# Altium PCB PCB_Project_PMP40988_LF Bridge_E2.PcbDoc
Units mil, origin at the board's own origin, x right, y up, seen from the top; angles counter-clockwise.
Board outline 1299.21 x 1322.83 mil, 2 copper layers (Top Layer, Bottom Layer), stack 64.8 mil thick; 14 components, 7 nets, 30 pads, 453 vias.
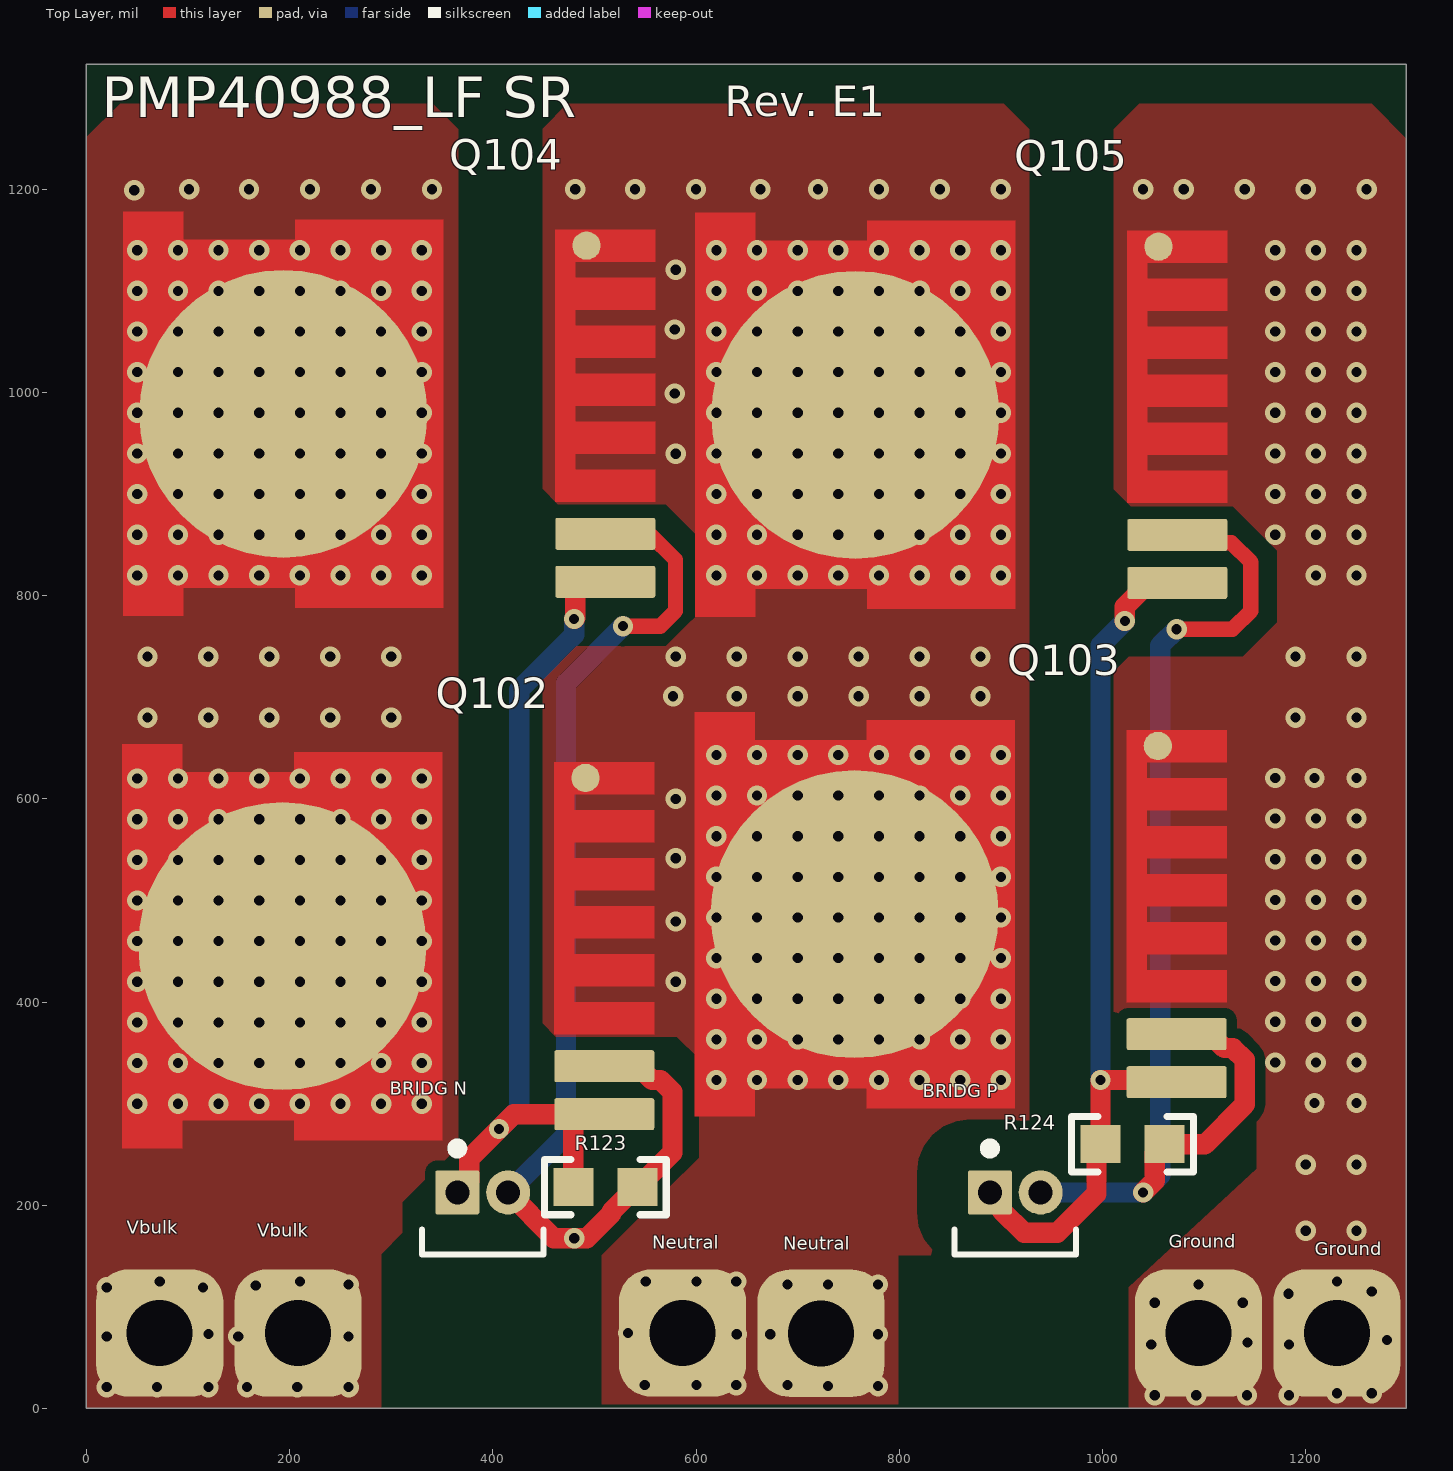
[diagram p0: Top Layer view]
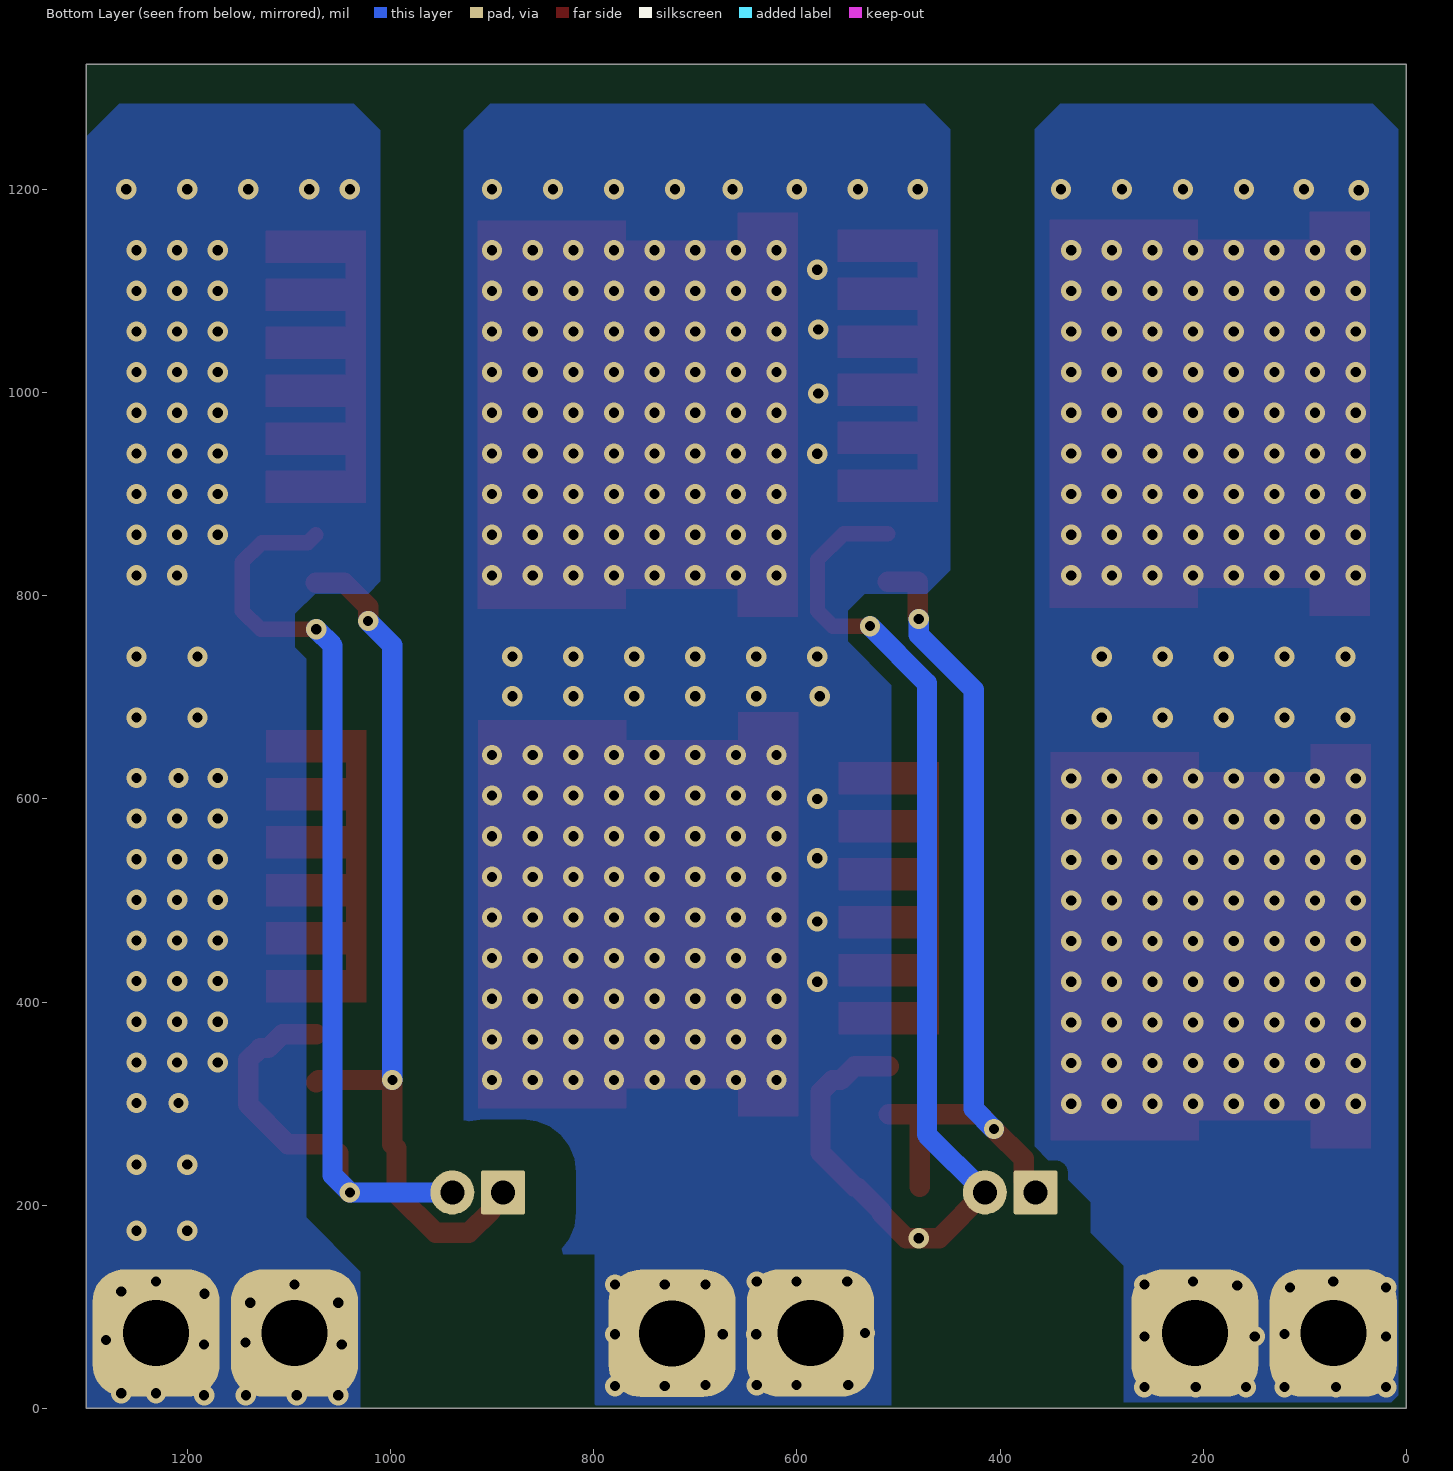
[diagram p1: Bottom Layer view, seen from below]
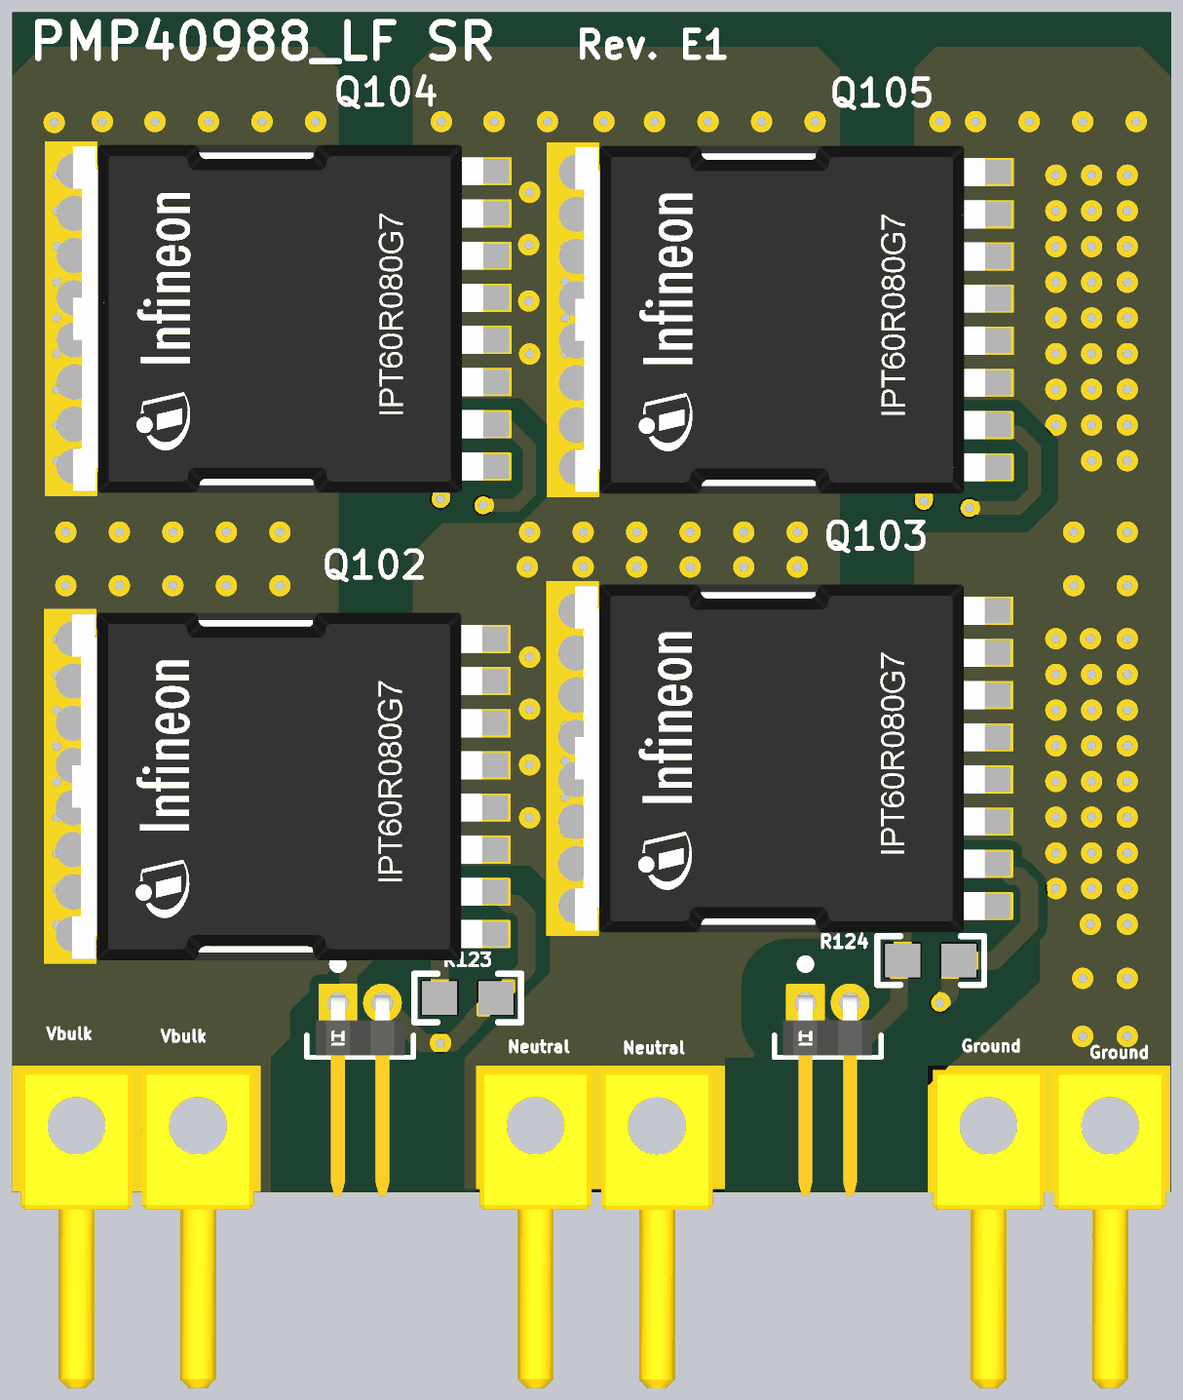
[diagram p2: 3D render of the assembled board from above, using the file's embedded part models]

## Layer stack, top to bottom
Top Solder: solder mask 0.4, Solder Resist, Dk 3.5
Top Layer: signal copper 2.8
Dielectric1: core 59.2, FR-4 High Tg, Dk 4.8
Bottom Layer: signal copper 2.8
Bottom Solder: solder mask 0.4, Solder Resist, Dk 3.5

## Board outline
0,0 0,1322.83 1299.21,1322.83 1299.21,0 925.2,0 767.72,0 393.7,0 278.35,0

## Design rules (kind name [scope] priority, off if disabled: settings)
AcuteAngle [All] p1: minimum=4.50000000000000E+0001 checktracksonly=FALSE
AssemblyTestPointUsage [All] p1: valid=2
Clearance Clearance_3 [InNet('EARTH') vs Not InNet('EARTH') And Not InNet('12VS')] p1: gap=200 ignorepadtopadclearanceinfootprint=FALSE except(0: Arc-Hole Track-Hole SMDPad-Hole THPad-Hole Via-Hole Fill-Hole Poly-Hole Region-Hole Text-Hole)
Clearance Clearance_1 [InNetClass('HV') vs InNetClass('MV')] p2: gap=25 ignorepadtopadclearanceinfootprint=FALSE except(0: Arc-Hole Track-Hole SMDPad-Hole THPad-Hole Via-Hole Fill-Hole Poly-Hole Region-Hole Text-Hole)
Clearance Clearance_2 [InNetClass('HV') vs Not InNetClass('HV')] p3: gap=50 ignorepadtopadclearanceinfootprint=FALSE except(0: Arc-Hole Track-Hole SMDPad-Hole THPad-Hole Via-Hole Fill-Hole Poly-Hole Region-Hole Text-Hole)
Clearance Clearance_Keepouts [((IsTrack Or IsArc) And Not InPoly) And IsFree and IsKeepOut vs ((IsTrack Or IsArc) And Not InPoly) And IsFree and IsKeepOut] p4: gap=0 ignorepadtopadclearanceinfootprint=FALSE
Clearance Clearance_BoardEdge_MountingHoles [OnCopper and InComponentClass('Mounting Holes') vs IsKeepOut] p5: gap=40 ignorepadtopadclearanceinfootprint=FALSE except(0: Arc-Hole Track-Hole SMDPad-Hole THPad-Hole Via-Hole Fill-Hole Poly-Hole Region-Hole Text-Hole)
Clearance Clearance_BoardEdge_Poly [OnCopper and InPoly vs IsKeepOut] p6: gap=25 ignorepadtopadclearanceinfootprint=FALSE except(0: Arc-Hole Track-Hole SMDPad-Hole THPad-Hole Via-Hole Fill-Hole Poly-Hole Region-Hole Text-Hole)
Clearance Clearance_BoardEdge [OnCopper and Not InComponentClass('Logo') and not InComponentClass('FiducialMark') and not InRegion(1000,500,4000,800) and Not IsKeepout vs IsKeepOut] p7: gap=75 ignorepadtopadclearanceinfootprint=FALSE except(0: Arc-Hole Track-Hole SMDPad-Hole THPad-Hole Via-Hole Fill-Hole Poly-Hole Region-Hole Text-Hole)
Clearance Clearance_Poly [InPolygon] p8: gap=10 ignorepadtopadclearanceinfootprint=FALSE except(0: Arc-Hole Track-Hole SMDPad-Hole THPad-Hole Via-Hole Fill-Hole Poly-Hole Region-Hole Text-Hole)
Clearance [All] p9: gap=7.87 ignorepadtopadclearanceinfootprint=TRUE except(0: Arc-Hole Track-Hole SMDPad-Hole THPad-Hole Via-Hole Fill-Hole Poly-Hole Region-Hole Text-Hole)
ComponentClearance ComponentClearance_HeatSink [Identifier = 'Heat Sink'] p1: gap=0 collisioncheckmode=3 verticalgap=0 showdistances=FALSE
ComponentClearance ComponentClearance_MountingHoles_FiducialMarks [InComponentClass('Mounting Holes') vs InComponentClass('FiducialMark')] p2: gap=20 collisioncheckmode=3 verticalgap=10 showdistances=FALSE
ComponentClearance ComponentClearance_Shunt [InComponentClass('Header') vs InComponentClass('Shunt')] p3: gap=0 collisioncheckmode=3 verticalgap=0 showdistances=FALSE
ComponentClearance ComponentClearance_Logo [InComponentClass('Logo')] p4: gap=5 collisioncheckmode=3 verticalgap=10 showdistances=FALSE
ComponentClearance ComponentClearance_ScrewToNut [(HasFootprint('NY PMS 440 0025 PH')) vs (HasFootprint('Keystone_1902C'))] p5: gap=20 collisioncheckmode=3 verticalgap=100000 showdistances=FALSE
ComponentClearance ComponentClearance_MountingHoles [InComponentClass('Mounting Holes')] p6: gap=20 collisioncheckmode=3 verticalgap=10 showdistances=FALSE
ComponentClearance ComponentClearance_SmallPassives [HasFootprint('0201*') or HasFootprint('0402*') or HasFootprint('0508') or HasFootprint('0603*') or HasFootprint('0612') or HasFootprint('0805*') or HasFootprint('0815*') or HasFootprint('0830*') or HasFootprint('1206*') or HasFootprint('1210*') or HasFootprint('1808*') or HasFootprint('1812*') or HasFootprint('1825*') or HasFootprint('2010*') or HasFootprint('2220*') or HasFootprint('2225*') or HasFootprint('2512*') or HasFootprint('2728*') or HasFootprint('3518*') vs HasFootprint('0201*') or HasFootprint('0402*') or HasFootprint('0508') or HasFootprint('0603*') or HasFootprint('0612') or HasFootprint('0805*') or HasFootprint('0815*') or HasFootprint('0830*') or HasFootprint('1206*') or HasFootprint('1210*') or HasFootprint('1808*') or HasFootprint('1812*') or HasFootprint('1825*') or HasFootprint('2010*') or HasFootprint('2220*') or HasFootprint('2225*') or HasFootprint('2512*') or HasFootprint('2728*') or HasFootprint('3518*')] p7: gap=20 collisioncheckmode=3 verticalgap=20 showdistances=FALSE
ComponentClearance ComponentClearance_THtoSMT [IsThruComponent vs IsSMTComponent] p8: gap=10 collisioncheckmode=3 verticalgap=10 showdistances=FALSE
ComponentClearance ComponentClearance_THtoTH [IsThruComponent vs IsThruComponent] p9: gap=10 collisioncheckmode=3 verticalgap=10 showdistances=FALSE
ComponentClearance [All] p10: gap=10 collisioncheckmode=3 verticalgap=10 showdistances=FALSE
DiffPairsRouting [All] p1: maxlimit=100 minlimit=10 mostfreqgap=10 toplayer_minwidth=15 toplayer_maxwidth=15 toplayer_prefwidth=15 bottomlayer_minwidth=15 bottomlayer_maxwidth=15 bottomlayer_prefwidth=15 maxuncoupledlength=1000
FabricationTestPointUsage TestPointUsage [All] p1: valid=2 allowmultiple=FALSE
FabricationTestpoint Testpoint [All] p1: side=3 testpointundercomponent=TRUE minsize=40 maxsize=100 preferedsize=60 minholesize=0 maxholesize=40 preferedholesize=32 testpointgrid=1 allowsidetop=TRUE allowsidebottom=TRUE usegrid=TRUE gridtolerance=0.01
FanoutControl Fanout_LCC [IsLCC] p1: bgadir=Out bgaviamode=Centered fanoutstyle=Auto fanoutdirection=Alternating viagrid=1 // Fanout_LCC (Default Rule)
FanoutControl Fanout_BGA [IsBGA] p2: bgadir=Out bgaviamode=Centered fanoutstyle=Auto fanoutdirection=Alternating viagrid=1 // Fanout_BGA (Default Rule)
FanoutControl Fanout_Default [All] p4: bgadir=Out bgaviamode=Centered fanoutstyle=Auto fanoutdirection=Alternating viagrid=1 // Fanout_Default (Default Rule)
FanoutControl Fanout_Small [(CompPinCount < 5)] p5: bgadir=Out bgaviamode=Centered fanoutstyle=Auto fanoutdirection=OutThenIn viagrid=1 // Fanout_Small (Default Rule)
Height [All] p1: minheight=0 maxheight=3000 prefheight=500
HoleSize [All] p1: absolutevalues=TRUE maxlimit=251 minlimit=7 maxpercent=80.000 minpercent=20.000
MinimumAnnularRing MinimumAnnularRing_ThermalPadVias [IsVia and InAnyComponent] p1: minimumring=5.91
MinimumAnnularRing [All] p2: minimumring=4.9
MinimumSolderMaskSliver MinimumSolderMaskSliver_Logo [InComponentClass('Logo') vs InComponentClass('Logo')] p1: minsoldermaskwidth=0.7
MinimumSolderMaskSliver [All] p2: minsoldermaskwidth=2
PlaneConnect [All] p1: planeconnectstyle=Direct reliefexpansion=10 reliefentries=4 reliefconductorwidth=10 reliefairgap=10
PolygonConnect [All] p1: connectstyle=Direct reliefconductorwidth=10 reliefentries=4 polygonreliefangle="90 Angle" airgapwidth=10
RoutingVias ThermalPadVias [IsVia and InAnyComponent] p1: holewidth=7.87 width=19.68 viastyle="Through Hole" minholewidth=7.87 minwidth=19.68 maxholewidth=12.99 maxwidth=23.62
RoutingVias [All] p2: holewidth=16 width=34 viastyle="Through Hole" minholewidth=7.87 minwidth=20 maxholewidth=40 maxwidth=65
SilkToBoardRegionClearance [Not ((IsComment or IsDesignator) And (Hide <> 'False')) and not InRegion(1000,500,4000,800)] p1:
SilkToSilkClearance SilkToSilkClearance_Pb-FreeLogo [(HasFootprint('Pb-Free_Overlay_Medium') OR HasFootprint('Pb-Free_Overlay_Small')) vs (HasFootprint('Pb-Free_Overlay_Medium') OR HasFootprint('Pb-Free_Overlay_Small'))] p1: silktosilkclearance=0
SilkToSilkClearance [All] p2: silktosilkclearance=1
SilkToSolderMaskClearance "Silk to Solder Mask Opening" [All] p1: minsilkscreentomaskgap=1 clearancetoexposedcopper=FALSE
SolderMaskExpansion [All] p1: expansion=1.97 istentingtop=FALSE
Width [All] p1: maxlimit=100 minlimit=6 preferedwidth=10 checkconnectedcopper=TRUE
14 further rules are at their usual default settings.

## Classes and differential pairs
net class HV: +BRDG_N -BRDG_N Neutral Vbulk
component class "PCB_Project_PMP40988_LF Bridge": "BRIDG N" "BRIDG P" Ground Neutral Q102 Q103 Q104 Q105 R123 R124 Vbulk

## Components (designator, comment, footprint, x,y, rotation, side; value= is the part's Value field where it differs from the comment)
"BRIDG N" "M50-3930242" FP-M50-3930242_HDR2-MFG 390,173.23 r0 top
"BRIDG P" "M50-3930242" FP-M50-3930242_HDR2-MFG 914.18,173.23 r0 top
Ground "3621-0-32-15-00-00-08-0" Mill-Max_3621-0-32-xx-00-00-08-0 1230.71,-19.68 r0 top
Ground "3621-0-32-15-00-00-08-0" Mill-Max_3621-0-32-xx-00-00-08-0 1094.49,-19.68 r0 top
Neutral "3621-0-32-15-00-00-08-0" Mill-Max_3621-0-32-xx-00-00-08-0 722.83,-20 r0 top
Neutral "3621-0-32-15-00-00-08-0" Mill-Max_3621-0-32-xx-00-00-08-0 586.61,-19.68 r0 top
Q102 "IPT60R022S7XTMA1" FP-IPT60R080G7XTMA1_HSOF-8-MFG 299,455 r90 top
Q103 "IPT60R022S7XTMA1" FP-IPT60R080G7XTMA1_HSOF-8-MFG 862.37,486.5 r90 top
Q104 "IPT60R022S7XTMA1" FP-IPT60R080G7XTMA1_HSOF-8-MFG 300,979 r90 top
Q105 "IPT60R022S7XTMA1" FP-IPT60R080G7XTMA1_HSOF-8-MFG 863,978 r90 top
R123 "RC0603FR-07100KL" 0603 510.63,218 r180 top value=100k
R124 "RC0603FR-07100KL" 0603 1029.61,260.07 r180 top value=100k
Vbulk "3621-0-32-15-00-00-08-0" Mill-Max_3621-0-32-xx-00-00-08-0 72.05,-19.68 r0 top
Vbulk "3621-0-32-15-00-00-08-0" Mill-Max_3621-0-32-xx-00-00-08-0 208.27,-19.68 r0 top

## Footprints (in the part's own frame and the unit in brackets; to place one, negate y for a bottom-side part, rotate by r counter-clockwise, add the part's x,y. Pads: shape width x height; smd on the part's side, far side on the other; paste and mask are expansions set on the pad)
0603 [mm] "0603 from SM-752 data"
  rect 1x0.95 smd: 1(-0.8,0) 2(0.8,0)
  silkscreen extent -1.52,-0.69 1.52,0.69, body extent -0.87,-0.47 0.87,0.47, height 1
FP-IPT60R080G7XTMA1_HSOF-8-MFG [mm]
  rrect13% 0.8x2.5 smd paste-1000 mask+0: 1(-4.2,-5.35) 2(-3,-5.35)
  round 0.709 smd paste-1000 mask+0: 3-4-5-6-7-8(4.206,-4.881)
  round 7.2 smd paste-1000 mask+0: 9(0,2.7)
  Top Layer region: -4.85,-1.3 4.85,-1.3 4.85,2.4 4.35,2.4 4.35,5.2 5.05,5.2 5.05,6.7 -5.05,6.7 -5.05,5.2 -4.35,5.2 -4.35,2.4 -4.85,2.4
  Top Layer region: -2.2,-4.1 4.6,-4.1 4.6,-6.6 3.8,-6.6 3.8,-4.6 3.4,-4.6 3.4,-6.6 2.6,-6.6 2.6,-4.6 2.2,-4.6 2.2,-6.6 1.4,-6.6 1.4,-4.6 1,-4.6 1,-6.6 0.2,-6.6 0.2,-4.6 -0.2,-4.6 -0.2,-6.6 -1,-6.6 -1,-4.6 -1.4,-4.6 -1.4,-6.6 -2.2,-6.6 -2.2,-4.1
  body extent -5.15,-6.7 5.15,6.8, height 0.25
FP-M50-3930242_HDR2-MFG [mm]
  rrect9% 1.1x1.1 hole 0.6 paste-1000 mask+0: 1(-0.635,1)
  round 1.1 hole 0.6 paste-1000 mask+0: 2(0.635,1)
  silkscreen extent -1.52,-0.55 1.52,2.22, body extent -1.62,-4.85 1.62,1.65, height 0.25
Mill-Max_3621-0-32-xx-00-00-08-0 [mm] "PCB Pin, 0.04\" DIA, R/A, Edge-Mount"
  rrect50% 3.18x3.18 hole 1.65: 1(0,2.388)
  body extent -1.59,-5.06 1.59,3.98, height 1.57

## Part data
"BRIDG N" "BRIDG P": library part CMP-0097272-1, "Conn Unshrouded HDR 2 POS 1.27mm Solder RA Through Hole Box", Current_A=1A, Digikey Part Number=952-3614-ND, Manufacturer=Harwin, Mouser Part Number=855-M50-3930242, Operating Temperature Range="-40°C to +105°C"
Ground Ground Neutral Neutral Vbulk Vbulk: library part CMP-0082316-1, "PCB Pin, 0.04\" DIA, Edge-Mount", Manufacturer=Mill-Max, Supplier Part Number 1=575-3621032150000
Q102 Q103 Q104 Q105: library part CMP-0086487-1, "MOSFET N-CH 650V 23A HSOF-8", Manufacturer=Infineon
R123 R124: library part CMP-0022735-5, "RES, 100 k, 1%, 0.1 W, 0603", Manufacturer=Yageo, Power_W=100mW, Supplier Part Number 1=311-100KHRCT-ND, TempCo="100 ppm/C", Tolerance_%=1%, Value2=0.1W, Value_Code=100k

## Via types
v1: diameter 20, hole 10, Top Layer to Bottom Layer, 453 vias

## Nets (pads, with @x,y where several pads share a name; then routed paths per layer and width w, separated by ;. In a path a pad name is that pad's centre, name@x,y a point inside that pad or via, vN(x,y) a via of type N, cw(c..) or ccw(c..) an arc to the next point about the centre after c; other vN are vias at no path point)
+BRDG_N: "BRIDG N.1" Q102.1 Q104.1 R123.2 | length 862.4
  Top Layer w20: 365,212.6 376.65,224.25 376.65,245.65 v1(406,275) 420.65,289.65 Q102.1@484.88,289.65 ; R123.2 479.13,283.9 Q102.1@484.88,289.65 ; v1(480,777) 481.1,778.1 481.1,813.65 Q104.1 ; Q102.1 Q102.1@484.88,289.65
  Bottom Layer w20: v1(406,275) 426,295 426,707.42 480,761.42 v1(480,777)
+BRDG_P: "BRIDG P.1" Q103.1 Q105.1 R124.2 | length 867.2
  Top Layer w20: 889.18,212.37 900.83,200.72 900.83,194.82 922.81,172.84 955.55,172.84 994.08,211.37 994.08,256.04 R124.2 v1(998.12,323.27) 1070.87,323.27 Q103.1 ; v1(1022,775) 1022,789.2 1045.45,812.65 Q105.1
  Bottom Layer w20: v1(998.12,323.27) 998.12,751.12 v1(1022,775)
-BRDG_N: "BRIDG N.2" Q102.2 Q104.2 R123.1 | length 1145.8
  Top Layer w15: Q104.2 554.11,860.89 579.62,835.38 579.62,784.8 564.82,770 v1(528,770)
  Top Layer w20: 415,212.6 460.02,167.58 492.38,167.58 516.69,191.9 516.69,193.55 541.14,218 543.11,218 576.72,251.61 576.72,311.6 565.05,323.27 556.72,323.27 543.09,336.89 Q102.2
  Bottom Layer w20: 415,212.6 472,269.6 472,714 v1(528,770)
  other v1: 480.1,167.58
-BRDG_P: "BRIDG P.2" Q103.2 Q105.2 R124.1 | length 1120.4
  Top Layer w15: v1(1073,767) 1128,767 1146,785 1146,833 1127,852 1081.52,852 Q105.2
  Top Layer w20: v1(1040,212.6) 1051.43,224.02 R124.1@1051.43,251.37 ; R124.1 1100.97,260.07 1140.09,299.19 1140.09,343.09 1128.42,354.76 1120.09,354.76 1106.46,368.39 Q103.2
  Bottom Layer w20: 959.82,212.6 v1(1040,212.6) 1057,229.6 1057,751 v1(1073,767)
Neutral: Neutral.1 Q102.3-4-5-6-7-8 Q103.9 Q104.3-4-5-6-7-8 Q105.9
  other v1: 730,22 779,22 549.5,23 600.5,23 639.5,23 690,23 640,73 673,73 779,73 533,74.32 690,122 730,122 779,122 550.5,125 600.5,125 639.5,125 620,323.27 660,323.27 700,323.27 740,323.27 780,323.27 820,323.27 860,323.27 900,323.27 620,363.27 660,363.27 700,363.27 740,363.27 780,363.27 820,363.27 860,363.27 900,363.27 620,403.27 660,403.27 700,403.27 740,403.27 780,403.27 820,403.27 860,403.27 900,403.27 580,420 620,443.27 660,443.27 700,443.27 740,443.27 780,443.27 820,443.27 860,443.27 900,443.27 580,479.27 620,483.27 660,483.27 700,483.27 740,483.27 780,483.27 820,483.27 860,483.27 900,483.27 620,523.27 660,523.27 700,523.27 740,523.27 780,523.27 820,523.27 860,523.27 900,523.27 580,541.61 620,563.27 660,563.27 700,563.27 740,563.27 780,563.27 820,563.27 860,563.27 900,563.27 580,600 620,603.27 660,603.27 700,603.27 740,603.27 780,603.27 820,603.27 860,603.27 900,603.27 620,643.27 660,643.27 700,643.27 740,643.27 780,643.27 820,643.27 860,643.27 900,643.27 577.44,701 640,701 700,701 760,701 820,701 880,701 580,740 640,740 700,740 760,740 820,740 880,740 620,820 660,820 700,820 740,820 780,820 820,820 860,820 900,820 620,860 660,860 700,860 740,860 780,860 820,860 860,860 900,860 620,900 660,900 700,900 740,900 780,900 820,900 860,900 900,900 580,939.63 620,940 660,940 700,940 740,940 780,940 820,940 860,940 900,940 620,980 660,980 700,980 740,980 780,980 820,980 860,980 900,980 579,999 620,1020 660,1020 700,1020 740,1020 780,1020 820,1020 860,1020 900,1020 620,1060 660,1060 700,1060 740,1060 780,1060 820,1060 860,1060 900,1060 579,1062 620,1100 660,1100 700,1100 740,1100 780,1100 820,1100 860,1100 900,1100 580,1120.73 620,1140 660,1140 700,1140 740,1140 780,1140 820,1140 860,1140 900,1140 481.1,1200 540,1200 600,1200 663.28,1200 720,1200 780,1200 840,1200 900,1200
PGND: Ground.1 Q103.3-4-5-6-7-8 Q105.3-4-5-6-7-8
  other v1: 1051.43,13 1092.31,13 1142.31,13 1183.42,13 1230.71,15 1265,15 1048,63 1183.42,63 1142.84,65 1280,67.32 1051.43,104 1138,104 1183,113 1265,115 1094.49,122 1230.71,125 1200,175 1250,175 1200,240 1250,240 1208.63,300.6 1250,300.6 1170,340.6 1210,340.6 1250,340.6 1170,380.6 1210,380.6 1250,380.6 1170,420.6 1210,420.6 1250,420.6 1170,460.6 1210,460.6 1250,460.6 1170,500.6 1210,500.6 1250,500.6 1170,540.6 1210,540.6 1250,540.6 1170,580.6 1210,580.6 1250,580.6 1170,620.6 1208.63,620.6 1250,620.6 1190,680 1250,680 1190,740 1250,740 1210,820 1250,820 1170,860 1210,860 1250,860 1170,900 1210,900 1250,900 1170,940 1210,940 1250,940 1170,980 1210,980 1250,980 1170,1020 1210,1020 1250,1020 1170,1060 1210,1060 1250,1060 1170,1100 1210,1100 1250,1100 1170,1140 1210,1140 1250,1140 1040,1200 1080,1200 1140,1200 1200,1200 1260,1200
Vbulk: Q102.9 Q104.9 Vbulk.1
  other v1: 20,21 69.42,21 120,21 158,21 207.42,21 258,21 20,71 149.39,71 258,71 120,73.17 20,119.22 114.7,119.22 166.58,121 258,122 72.05,125 210,125 50,300 90,300 130,300 170,300 210,300 250,300 290,300 330,300 50,340 90,340 130,340 170,340 210,340 250,340 290,340 330,340 50,380 90,380 130,380 170,380 210,380 250,380 290,380 330,380 50,420 90,420 130,420 170,420 210,420 250,420 290,420 330,420 50,460 90,460 130,460 170,460 210,460 250,460 290,460 330,460 50,500 90,500 130,500 170,500 210,500 250,500 290,500 330,500 50,540 90,540 130,540 170,540 210,540 250,540 290,540 330,540 50,580 90,580 130,580 170,580 210,580 250,580 290,580 330,580 50,620 90,620 130,620 170,620 210,620 250,620 290,620 330,620 60,680 120,680 180,680 240,680 300,680 60,740 120,740 180,740 240,740 300,740 50,820 90,820 130,820 170,820 210,820 250,820 290,820 330,820 50,860 90,860 130,860 170,860 210,860 250,860 290,860 330,860 50,900 90,900 130,900 170,900 210,900 250,900 290,900 330,900 50,940 90,940 130,940 170,940 210,940 250,940 290,940 330,940 50,980 90,980 130,980 170,980 210,980 250,980 290,980 330,980 50,1020 90,1020 130,1020 170,1020 210,1020 250,1020 290,1020 330,1020 50,1060 90,1060 130,1060 170,1060 210,1060 250,1060 290,1060 330,1060 50,1100 90,1100 130,1100 170,1100 210,1100 250,1100 290,1100 330,1100 50,1140 90,1140 130,1140 170,1140 210,1140 250,1140 290,1140 330,1140 47,1199 101,1200 160,1200 220,1200 280,1200 340,1200

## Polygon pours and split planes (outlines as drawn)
PGND on Top Layer "Top Layer-No Net 1" (solid, remove dead copper, pour order 2): 1265,1284 1299.21,1249.79 1299.21,0 1026,0 1026,119.22 1152,236 1152,349 1132.61,368.39 1029.61,368.39 1011,387 1011,725 1026,740 1138,740 1172,774 1172,844 1128,888 1027.8,888 1011,904.8 1011,1259 1036,1284
Vbulk on Top Layer "Top Layer-No Net" (solid, remove dead copper, pour order 0): 33,1284 341,1284 366,1259 366,258 311,203 311,173 290,152 290,0 0,0 0,1251
Neutral on Top Layer "Top Layer-No Net 2" (solid, remove dead copper, pour order 4): 903,1284 928,1259 928,273 873,218 873,169 855,151 799,151 799,4 506.98,4 506.98,150.98 603,247 603,344 581,366 462,366 449,379 449,717 482,750 570,750 599,779 599,861 570,890 464,890 449,905 449,1259.58 473.42,1284
Neutral on Bottom Layer "Bottom Layer-No Net 1" (solid, remove dead copper, pour order 10): 902,1284 474,1284 449,1259 449,825 472,802 533,802 550,785 550,755 506.98,711.98 506.98,3 798,3 799,4 799,152 857,152 874,169 874,218 928,272 928,1258
PGND on Bottom Layer "Bottom Layer-No Net" (solid, remove dead copper, pour order 8): 1010,1258 1010,814 1022,802 1074,802 1094,782 1094,749 1083,738 1083,188.02 1029.61,134.63 1029.61,0 1299.21,0 1299.21,1251.79 1267,1284 1036,1284
Vbulk on Bottom Layer "Top Layer-No Net" (solid, remove dead copper, pour order 6): 33,1284 341,1284 366,1259 366,258 311,203 311,173 278.35,140.35 278.35,6 15,6 8,13 8,1259

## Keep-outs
Keep-Out Layer:
  text ".Layer_Name" at -945,-1745.76 h60

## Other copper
Top Layer:
  text ".Layer_Name" at -945,-1745.76 h60
Bottom Layer:
  text ".Layer_Name" at -945,-1745.76 h60

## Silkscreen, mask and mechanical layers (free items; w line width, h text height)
Top Overlay:
  text "Rev. E1" at 628,1272 h30
  text "PMP40988_LF SR" at 15,1271 h40
  text ".Layer_Name" at -945,-1745.76 h60
Bottom Overlay:
  text ".Layer_Name" at -945,-1745.76 h60
Top Paste:
  text ".Layer_Name" at -945,-1745.76 h60
Bottom Paste:
  text ".Layer_Name" at -945,-1745.76 h60
Top Solder:
  rectangle: 1026,0 1298,142
  rectangle: 520,0 799,142
  rectangle: 0,1 278.35,142
  text ".Layer_Name" at -945,-1745.76 h60
  text ".Layer_Name" at -945,-1745.76 h60
Bottom Solder:
  rectangle: 1018,814 1270,1268
  rectangle: 554,707 926,865
  rectangle: 470,859 926,1268
  rectangle: 1027.8,0 1299,140.35
  rectangle: 521.5,1 818,143
  rectangle: 0,1 290,142
  rectangle: 33,247 356,1268
  rectangle: 533,250 926,707
  rectangle: 1101,252 1270,818
  text ".Layer_Name" at -945,-1745.76 h60
Drill Guide:
  text ".Layer_Name" at -945,-1745.76 h60
M1 Board Outline:
  the board outline again, w10
  text ".Layer_Name" at -945,-1745.76 h60
M2 Board Dimensions:
  rectangle: -1397,-1287.27 -1022,-1162.27
  rectangle: -1522,-1162.27 -1397,-1037.27
  lines w7: -1522,-1162.27 -522,-1162.27 ; -1397,-1287.27 -1397,-1037.27 ; -1272,-1287.27 -1272,-1037.27 ; -1022,-1287.27 -1022,-1037.27 ; -772,-1287.27 -772,-1037.27 ; -1522,-1287.27 -1522,-1037.27 -522,-1037.27 -522,-1287.27 -1522,-1287.27
  text ".Layer_Name" at -945,-1745.76 h60
M3 3D STEP Top:
  text ".Layer_Name" at -945,-1745.76 h60
M4 3D STEP Bottom:
  text ".Layer_Name" at -945,-1745.76 h60
M5 Assembly Top:
  lines w10: -1814,-1817.43 4786,-1817.43 ; -1814,-1614.1 4788,-1614.1 ; -1814,-1410.77 -1814,-2020.77 2191,-2020.77 4788,-2020.77 4788,-1410.77 -1813.5,-1410.77 -1813.5,-2020.77 -238,-2020.77 ; 651,-2020.77 651,-1410.77 ; 1918,-1614.1 1918,-1410.77 ; 2758,-1614.1 2758,-1410.77 ; 3380,-2027.27 3380,-1824.43
  text "COMPONENTS MARKED 'DNP' SHOULD NOT BE POPULATED." at -368.5,-1205.77 h60
  text "ASSEMBLY VARIANT:" at -369,-1321.27 h60
  text ".VariantName" at 667,-1321.27 h60
  text "PCB VIEWED FROM TOP SIDE" at -1750.5,-1542.93 h60
  text "BOARD #:" at 726,-1542.93 h60
  text ".PRJ_Number" at 1271.5,-1542.93 h60
  text "REV:" at 2116,-1542.93 h60
  text ".PCB_Rev" at 2407.5,-1542.93 h60
  text "SVN REV:" at 2954,-1542.93 h60
  text ".VersionControl_RevNumber" at 3460,-1542.93 h60
  text "TID #:" at 726,-1746.27 h60
  text ".TID" at 1271.5,-1746.27 h60
  text "PLOT NAME =" at -1750.5,-1951.6 h60
  text ".plot_File_Name" at -945,-1951.6 h60
  text "GENERATED    :" at 728,-1951.6 h60
  text ".Print_Date" at 1597.5,-1951.6 h60
  text ".Print_Time" at 2326.5,-1951.6 h60
  text "TEXAS INSTRUMENTS" at 3591,-1951.6 h60
M6 Assembly Bottom:
  lines w10: -1814.5,-1614.6 4787.5,-1614.6 ; -1812.5,-1817.93 4787.5,-1817.93 ; -406.5,-2027.77 -406.5,-1824.93 ; 215.5,-1614.6 215.5,-1411.27 ; 1055.5,-1614.6 1055.5,-1411.27 ; 2322.5,-2021.27 2322.5,-1411.27 ; 3211.5,-2021.27 4787,-2021.27 4787,-1411.27 -1814.5,-1411.27 -1814.5,-2021.27 782.5,-2021.27 4787.5,-2021.27 4787.5,-1411.27
  text "COMPONENTS MARKED 'DNP' SHOULD NOT BE POPULATED." at 4580,-1205.27 h60
  text ".VariantName" at 3536,-1321.27 h60
  text "ASSEMBLY VARIANT:" at 4575,-1321.27 h60
  text ".VersionControl_RevNumber" at -486.5,-1543.43 h60
  text "SVN REV:" at 19.5,-1543.43 h60
  text ".PCB_Rev" at 566,-1543.43 h60
  text "REV:" at 857.5,-1543.43 h60
  text ".PRJ_Number" at 1702,-1543.43 h60
  text "BOARD #:" at 2247.5,-1543.43 h60
  text "PCB VIEWED FROM BOTTOM SIDE" at 4724,-1543.43 h60
  text ".TID" at 1702,-1746.77 h60
  text "TID #:" at 2247.5,-1746.77 h60
  text "TEXAS INSTRUMENTS" at -617.5,-1952.1 h60
  text ".Print_Time" at 647,-1952.1 h60
  text ".Print_Date" at 1376,-1952.1 h60
  text "GENERATED    :" at 2245.5,-1952.1 h60
  text ".plot_File_Name" at 3918.5,-1952.1 h60
  text "PLOT NAME =" at 4724,-1952.1 h60
M9 Title Sheet:
  drawing of 57 lines, arcs and shapes, not listed
  text "1" at -782.16,7149.23 h70
  text "2" at 1713.5,7149.23 h70
  text "3" at 4202.84,7149.23 h70
  text "4" at 6709.51,7149.23 h70
  text "5" at 9208.5,7149.23 h70
  text "6" at 11713.5,7149.23 h70
  text "A" at -1938.5,6006.23 h70
  text "A" at 12861.5,6006.23 h70
  text "B" at -1938.5,3626.23 h70
  text "B" at 12861.5,3626.23 h70
  text "C" at -1938.5,1251.23 h70
  text "C" at 12861.5,1251.23 h70
  text "PROJECT TITLE:" at 9821.5,-609.77 h45
  text ".PRJ_Title" at 9871.5,-743.09 h70
  text "DESIGNED FOR:" at 9821.5,-910.77 h45
  text ".PRJ_Customer" at 9871.5,-1050.77 h70
  text "D" at -1938.5,-1118.77 h70
  text "D" at 12861.5,-1118.77 h70
  text "FILE NAME:" at 9821.5,-1210.77 h45
  text ".PCB_File_Name_No_Path" at 9871.5,-1330.77 h70
  text "Texas Instruments (TI) and/or its licensors do not warrant the accuracy or completeness of this specification" at 4852,-1492.61 h45
  text "ENGINEER:" at 9821.5,-1500.77 h45
  text "LAYOUT BY:" at 11326.5,-1500.77 h45
  text "or any information contained therein. TI and/or its licensors do not warrant that this design will meet" at 4807.01,-1605.27 h45
  text ".PRJ_Engineer" at 9871.5,-1655.76 h70
  text ".PCB_Layout" at 11377,-1655.76 h70
  text "the specifications, will be suitable for your application or fit for any particular purpose, or will operate in" at 4807.01,-1717.94 h45
  text ".Layer_Name" at -945,-1745.76 h60
  text "ALTIUM DESIGNER VERSION:" at 11326.5,-1810.77 h45
  text "an implementation. TI and/or its licensors do not warrant that the design is production worthy. You should" at 4807.01,-1830.6 h45
  text "completely validate and test your design implementation to confirm the system functionality for your application." at 4852,-1943.27 h45
  text ".print_Scale" at 9871.5,-1944.09 h70
  text ".Application_BuildNumber" at 11377,-1944.09 h70
  text "1" at -782.16,-2150.77 h70
  text "2" at 1713.5,-2150.77 h70
  text "3" at 4202.84,-2150.77 h70
  text "4" at 6709.51,-2150.77 h70
  text "5" at 9208.5,-2150.77 h70
  text "6" at 11713.5,-2150.77 h70
M10 Fab Notes:
  drawing of 189 lines, arcs and shapes, not listed
  text "DESIGN INFORMATION" at 10860.02,5468.91 h60
  text "MIN. TRACK WIDTH:" at 10215.46,5336.78 h60
  text "8" at 11311.7,5336.78 h60
  text "MIL" at 11466.46,5336.78 h60
  text "7.874" at 11145.32,5215.09 h60
  text "MIN. CLEARANCE:" at 10215.46,5212.65 h60
  text "MIL" at 11466.46,5212.65 h60
  text "MIN. VIA PAD SIZE:" at 10215.46,5088.53 h60
  text "24" at 11281.71,5088.53 h60
  text "MIL" at 11466.46,5088.53 h60
  text "0.05mm (2MIL)" at 10910.46,4958.63 h60
  text "MINIMUM ANNULAR RING" at 9886.23,4950.41 h60
  text "EXTERNAL" at 11618.46,4950.41 h60
  text "PER" at 10086.23,4840.28 h60
  text "IPC-D-275 CLASS 2 LEVEL C" at 10306.23,4840.28 h60
  text "MIL, HOLES" at 11794.46,4739.8 h60
  text "+/-" at 11402,4731.22 h60
  text "+/-" at 12256,4731.22 h60
  text "REGISTRATION TOLERANCES:" at 9886.23,4730.15 h60
  text "METAL" at 11086,4730.15 h60
  text "5" at 11662.2,4730.15 h60
  text "3" at 12495.2,4730.15 h60
  text "MIL" at 12611.46,4730.15 h60
  text "HOLE SIZE TOLERANCE (UNLESS OTHERWISE SPECIFIED):" at 9886.23,4631.84 h60
  text "+/-" at 12256,4628.96 h60
  text "3" at 12495.2,4627.9 h60
  text "MIL" at 12611.46,4627.9 h60
  text "MATERIAL:" at 9811.46,4490.25 h60
  text "FR-4 High Tg" at 10797.9,4361.73 h60
  text "X" at 10653.46,4353.74 h60
  text "FR-408" at 10232.46,4349.22 h60
  text "OTHER" at 11720.46,4349.22 h60
  text "62 MIL (1.6mm) +/-10%" at 10552.56,4206.19 h60
  text "X" at 10432.46,4203.74 h60
  text "THICKNESS:" at 9886.23,4197.97 h60
  text "OTHER" at 11837.46,4197.97 h60
  text "TOLERANCE:" at 9886.23,4059.65 h60
  text "X" at 10734.46,4059.65 h60
  text "ANSI IPC-6012 TYPE 3 CLASS 2" at 10912.48,4059.65 h60
  text "OTHER +/-" at 10912.46,3915.47 h60
  text "BOW & TWIST:" at 9886.23,3770.28 h60
  text "X" at 10734.46,3770.28 h60
  text "ANSI IPC-6012 TYPE 3 CLASS 2" at 10912.48,3770.28 h60
  text "OTHER +/-" at 10912.46,3623.58 h60
  text "DRILLING:" at 9811.46,3492.96 h60
  text "NC_DRILL FILES" at 11572.46,3387.77 h60
  text "REFERENCE:" at 9886.23,3383.84 h60
  text "X" at 10543.46,3383.74 h60
  text "AS SHOWN" at 10721.46,3383.84 h60
  text "X" at 11444.46,3383.84 h60
  text "OTHER" at 11870.46,3241.58 h60
  text "PTH COPPER THICKNESS:" at 9885.91,3238.06 h60
  text "X" at 11025.14,3238.06 h60
  text "20-30 um" at 11153.14,3238.06 h60
  text "BOARD FINISH:" at 9811.46,3090.46 h60
  text "SILKSCREEN:" at 9966.68,2980.33 h60
  text "X" at 10924.46,2980.33 h60
  text "TOP" at 11041.46,2980.33 h60
  text "X" at 11434.46,2980.33 h60
  text "BOTTOM" at 11552.46,2980.33 h60
  text "SILKSCREEN COLOR:" at 9966.68,2825.14 h60
  text "X" at 10923.46,2825.14 h60
  text "WHITE" at 11041.46,2825.14 h60
  text "OTHER" at 11552.46,2825.14 h60
  text "X" at 11054.46,2681.69 h60
  text "GREEN" at 11172.46,2681.69 h60
  text "OTHER" at 11790.46,2681.69 h60
  text "SOLDER RESIST COLOR:" at 9966.68,2674.83 h60
  text "X" at 11054.46,2527.44 h60
  text "MATTE" at 11172.46,2527.44 h60
  text "SEMI-GLOSS" at 11790,2526.8 h60
  text "IMMERSION GOLD (ENIG)" at 10872.46,2354.67 h60
  text "ENEPIG" at 12210,2347.45 h60
  text "SURFACE FINISH:" at 9811.46,2346.45 h60
  text "X" at 10694.46,2346.45 h60
  text "IMM. TIN/SILVER OR EQUIV" at 10141,2209.13 h60
  text "OTHER" at 11572.46,2205.2 h60
  text "ARRAY/PANEL:" at 9811.46,2049.82 h60
  text "CUT AND TRIM PER M1 BOARD OUTLINE" at 10872.46,2041.6 h60
  text "N.C. ROUTE" at 10872.46,1905.63 h60
  text "X" at 11560.46,1905.63 h60
  text "V. SCORE" at 11738.46,1905.63 h60
  text "CERTIFICATION:" at 9811.46,1776.5 h60
  text "MATERIALS AND WORKMANSHIP FOR ALL PCBS" at 10536.46,1776.5 h60
  text "TO MEET OR EXCEED THE REQUIREMENTS OF:" at 10536.46,1682.44 h60
  text "X" at 10173.97,1553.81 h60
  text "ANSI IPC-A-600F CLASS ->" at 10301.96,1553.81 h60
  text "X" at 11949.97,1553.81 h60
  text "2" at 12059.96,1553.81 h60
  text "1" at 11744.96,1552.32 h60
  text "3" at 12413.96,1552.32 h60
  text "X" at 10985.97,1406.13 h60
  text "RoHS" at 11113.96,1406.13 h60
  text "OTHER" at 11758.36,1406.13 h60
  text "PER ORDER" at 12155.42,1406.13 h60
  text "ALL BOARDS MUST MEET OR EXCEED UL94-V0 REQUIREMENTS." at 9839,1252.3 h60
  text "PCB MUST BEAR THE UL94V-0 UL REGISTERED MATERIAL ID NUMBER" at 9839,1136.24 h60
  text "ADDITIONAL REQUIREMENTS:" at 9811.46,966.81 h60
  text "MICROSECTION:" at 9886.23,859.69 h60
  text "YES" at 10791.96,859.69 h60
  text "REQUIRED" at 11653.46,715.35 h60
  text "BARE BOARD ELEC. TEST:" at 9886.23,712.5 h60
  text "NONE" at 11191.96,712.5 h60
  text "X" at 11535.46,712.5 h60
  text "PER ORDER" at 12245.46,712.5 h60
  text "XX MIL VIAS REQUIRE NON-CONDUCTIVE FILL AND PLANARIZE" at 10054.38,507.55 h59
  text "XX MIL VIAS REQUIRE CONDUCTIVE FILL AND PLANARIZE" at 10062.38,403.58 h60
  text "OUTER XX MIL TRACES REQUIRE 50 OHM SINGLE-ENDED IMPEDANCE" at 10061.39,240.19 h58
  text "LAYER 2 & 3 (INNER LAYERS) XX MIL WIDE, XX MIL SPACE / TRACES REQUIRE 100 OHM DIFFERENTIAL IMPEDANCE" at 10053.39,4.48 h60
  text ".Layer_Name" at -945,-1745.76 h60
M11 Gerber Information:
  lines w10: -1814,-1817.43 4786,-1817.43 ; -1814,-1614.1 4788,-1614.1 ; -1814,-1410.77 -1814,-2020.77 2191,-2020.77 4788,-2020.77 4788,-1410.77 -1813.5,-1410.77 -1813.5,-2020.77 -238,-2020.77 ; 651,-2020.77 651,-1410.77 ; 1918,-1614.1 1918,-1410.77 ; 2758,-1614.1 2758,-1410.77 ; 3380,-2027.27 3380,-1824.43
  text "ALL ARTWORK VIEWED FROM TOP SIDE" at -1750.5,-1542.93 h60
  text "BOARD #:" at 726,-1542.93 h60
  text ".PRJ_Number" at 1271.5,-1542.93 h60
  text "REV:" at 2116,-1542.93 h60
  text ".PCB_Rev" at 2407.5,-1542.93 h60
  text "SVN REV:" at 2954,-1542.93 h60
  text ".VersionControl_RevNumber" at 3460,-1542.93 h60
  text "LAYER NAME =" at -1750.5,-1745.76 h60
  text "TID #:" at 726,-1746.27 h60
  text ".TID" at 1271.5,-1746.27 h60
  text "PLOT NAME =" at -1750.5,-1951.6 h60
  text ".plot_File_Name" at -945,-1951.6 h60
  text "GENERATED    :" at 728,-1951.6 h60
  text ".Print_Date" at 1597.5,-1951.6 h60
  text ".Print_Time" at 2326.5,-1951.6 h60
  text "TEXAS INSTRUMENTS" at 3591,-1951.6 h60
M12 Stackup:
  drawing of 191 lines, arcs and shapes, not listed
  text "Layer" at 8299.59,6987.67 h60
  text "Name" at 8709.51,6987.67 h60
  text "Material" at 9639.25,6987.67 h60
  text "Thickness" at 10499.02,6987.67 h60
  text "Constant" at 11148.85,6987.67 h60
  text "Board Layer Stack" at 11718.71,6987.67 h60
  text "Top Overlay" at 8709.51,6867.67 h60
  text "Top Solder" at 8709.51,6747.67 h60
  text "Solder Resist" at 9639.25,6747.67 h60
  text "0.40mil" at 10499.02,6747.67 h60
  text "3.5" at 11148.85,6747.67 h60
  text "1" at 8299.59,6627.67 h60
  text "Top Layer" at 8709.51,6627.67 h60
  text "2.80mil" at 10499.02,6627.67 h60
  text "Dielectric1" at 8709.51,6507.67 h60
  text "FR-4 High Tg" at 9639.25,6507.67 h60
  text "59.20mil" at 10499.02,6507.67 h60
  text "4.8" at 11148.85,6507.67 h60
  text "2" at 8299.59,6387.67 h60
  text "Bottom Layer" at 8709.51,6387.67 h60
  text "2.80mil" at 10499.02,6387.67 h60
  text "Bottom Solder" at 8709.51,6267.67 h60
  text "Solder Resist" at 9639.25,6267.67 h60
  text "0.40mil" at 10499.02,6267.67 h60
  text "3.5" at 11148.85,6267.67 h60
  text "Bottom Overlay" at 8709.51,6147.67 h60
  text ".Layer_Name" at -945,-1745.76 h60
M13 Component Bodies Top:
  text ".Layer_Name" at -945,-1745.76 h60
M14 Component Bodies Bottom:
  text ".Layer_Name" at -945,-1745.76 h60
M15 Courtyards Top:
  text ".Layer_Name" at -945,-1745.76 h60
M16 Courtyards Bottom:
  text ".Layer_Name" at -945,-1745.76 h60
Drill Drawing:
  circle w10: c3841.72,2154.38 r27.63
  lines w10: 3814.09,2264.88 3827.9,2264.88 3841.72,2251.07 3855.53,2264.88 3869.34,2264.88 3855.53,2278.7 3869.34,2292.51 3855.53,2292.51 3841.72,2306.32 3827.9,2292.51 3814.09,2292.51 3827.9,2278.7 3814.09,2264.88 ; 3814.09,2375.39 3869.34,2375.39 3869.34,2430.64 3814.09,2430.64 3814.09,2375.39
  lines w12: 3764,2089.45 6995.49,2089.45 ; 3764,2462.41 6995.49,2462.41 ; 4101.86,1965.13 4101.86,2586.73 ; 4433.86,1965.13 4433.86,2586.73 ; 5070.43,1965.13 5070.43,2586.73 ; 5329.57,1965.13 5329.57,2586.73 ; 5704.72,1965.13 5704.72,2586.73 ; 6429.05,1965.13 6429.05,2586.73 ; 3764,1965.13 6995.49,1965.13 6995.49,2586.73 3764,2586.73 3764,1965.13
  text "Symbol" at 3838.59,2499.71 h72
  text "Quantity" at 4139.16,2499.71 h72
  text "Finished Hole Size" at 4471.16,2499.71 h72
  text "Plated" at 5107.72,2499.71 h72
  text "Hole Type" at 5366.86,2499.71 h72
  text "Drill Layer Pair" at 5742.02,2499.71 h72
  text "Hole Tolerance" at 6466.35,2499.71 h72
  text "453" at 4139.16,2375.39 h60
  text "10.00mil (0.254mm)" at 4471.16,2375.39 h60
  text "PTH" at 5107.72,2375.39 h60
  text "Round" at 5366.86,2375.39 h60
  text "Top Layer - Bottom Layer" at 5742.02,2375.39 h60
  text "4" at 4139.16,2251.07 h60
  text "23.62mil (0.600mm)" at 4471.16,2251.07 h60
  text "PTH" at 5107.72,2251.07 h60
  text "Round" at 5366.86,2251.07 h60
  text "Top Layer - Bottom Layer" at 5742.02,2251.07 h60
  text "6" at 4139.16,2126.75 h60
  text "64.96mil (1.650mm)" at 4471.16,2126.75 h60
  text "PTH" at 5107.72,2126.75 h60
  text "Round" at 5366.86,2126.75 h60
  text "Top Layer - Bottom Layer" at 5742.02,2126.75 h60
  text "463 Total" at 4139.16,2002.43 h60
  text ".Layer_Name" at -945,-1745.76 h60
M17 Embedded Cavity:
  text ".Layer_Name" at -945,-1745.76 h60
M18 Embedded Assembly:
  text ".Layer_Name" at -945,-1745.76 h60
M19 Embedded Keepout:
  text ".Layer_Name" at -945,-1745.76 h60

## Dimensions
-1522,-1287.27 to -522,-1287.27 on M2 Board Dimensions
